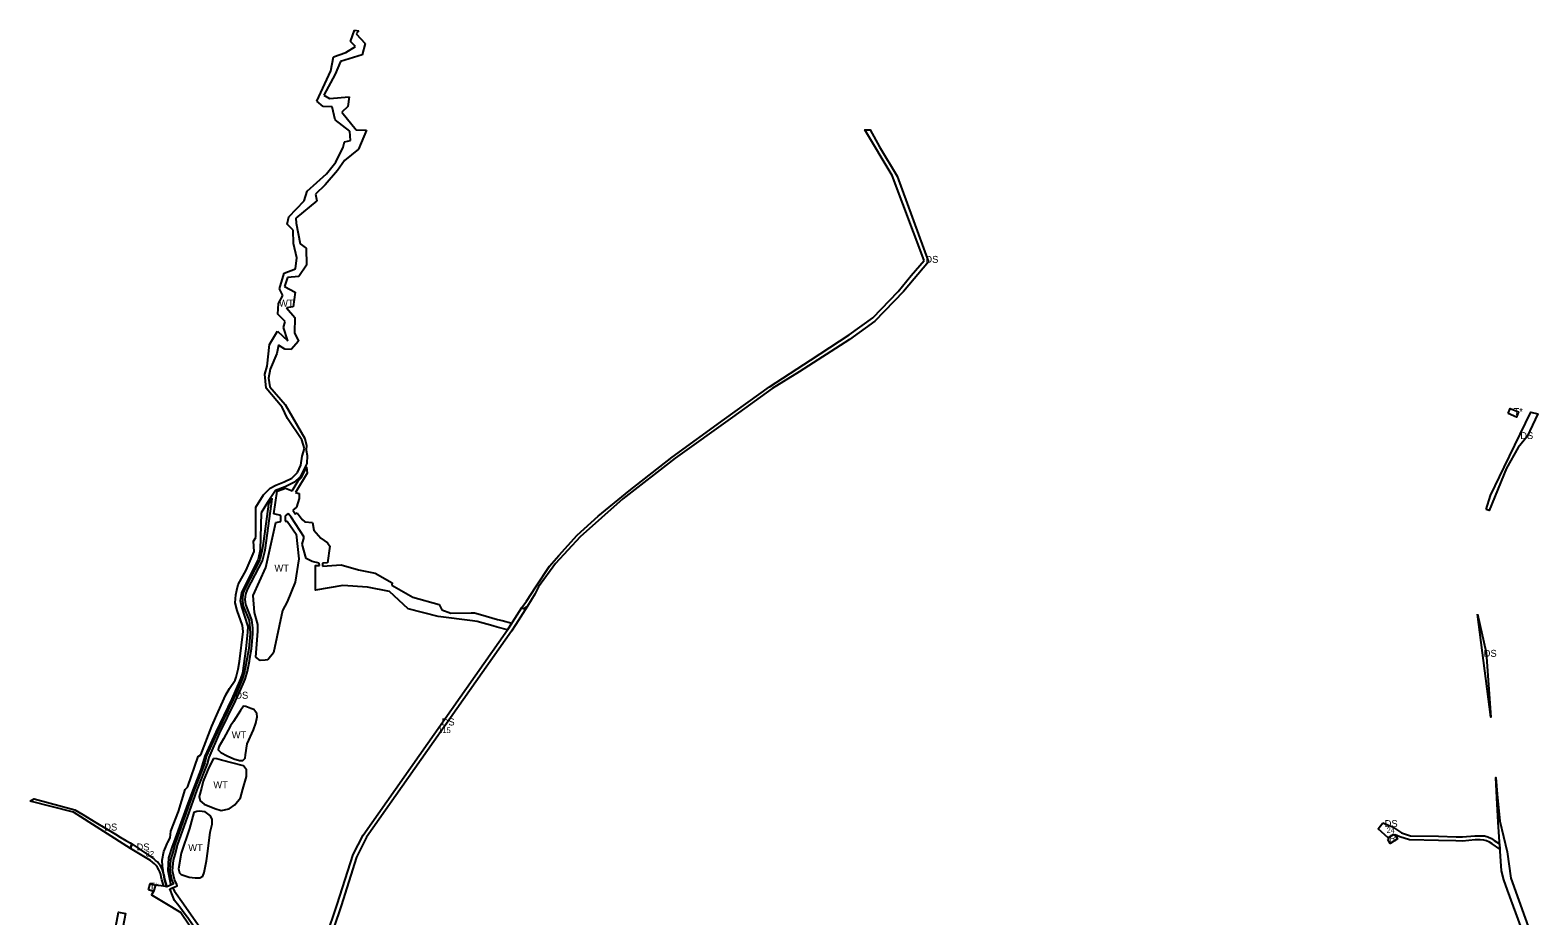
# Model space of a CAD drawing. Extents: x -521621 to -516769, y -1190068 to -1185078.
# Drawn here: x -519100 to -516936, y -1186349 to -1185078 of the extents above; entities that cross this region are included whole.
import ezdxf

# ---------------------------------------------------------------- set-up
doc = ezdxf.new("R2010")
doc.units = 0
for name, color, linetype in [('fpl_id', 7, 'Continuous'), ('rekreace_s', 7, 'Continuous'), ('v_infrastr_n', 7, 'Continuous'), ('v_infrastr_s', 7, 'Continuous'), ('voda_s', 7, 'Continuous')]:
    doc.layers.add(name, color=color, linetype=linetype)

msp = doc.modelspace()

# ---------------------------------------------------------------- linework, layer by layer
at = {"layer": 'rekreace_s'}
msp.add_lwpolyline([(-517151.5, -1186239.8), (-517150.1, -1186238.9), (-517150.8, -1186237.4), (-517145.5, -1186234), (-517143, -1186232.4), (-517142.2, -1186233.7), (-517140.8, -1186232.9), (-517137.3, -1186238.9), (-517142.6, -1186242.1), (-517148, -1186245.4)], close=True, dxfattribs=at)
at = {"layer": 'v_infrastr_n'}
for points in [[(-518690.9, -1186426.8), (-518659.5, -1186333), (-518636.5, -1186261.5), (-518622.2, -1186233.6), (-518414.9, -1185939), (-518414.9, -1185939), (-518408.8, -1185929.5), (-518407.8, -1185928), (-518394.2, -1185906.7), (-518391.7, -1185908.5), (-518385.9, -1185904.8), (-518402.8, -1185931.3), (-518409.2, -1185940.6), (-518409.2, -1185940.6), (-518409.2, -1185940.6), (-518617, -1186236.6), (-518631.4, -1186265.3), (-518653.7, -1186334.8), (-518685.1, -1186428.3)], [(-518927.4, -1186270), (-518955.8, -1186252.5), (-518953.9, -1186246.2), (-518922.6, -1186267.6)], [(-518908.2, -1186290.1), (-518907.1, -1186296.6), (-518903.9, -1186307.5), (-518908.2, -1186306.9), (-518911, -1186297.5), (-518911.7, -1186293.4)], [(-518980.6, -1186385), (-518973, -1186343.9), (-518963.1, -1186345.8), (-518970.7, -1186386.2)]]:
    msp.add_lwpolyline(points, dxfattribs=at)
msp.add_lwpolyline([(-517158.3, -1186215.8), (-517144.5, -1186221.5), (-517131.5, -1186230.4), (-517119, -1186234.4), (-517078.5, -1186235.2), (-517053.4, -1186235.8), (-517044.3, -1186236), (-517026.4, -1186234.3), (-517018.4, -1186234.3), (-517012.7, -1186234.7), (-517007.6, -1186235.8), (-517002.6, -1186238.4), (-516998.5, -1186241.1), (-516990.9, -1186246.1), (-516990.4, -1186253.6), (-517001.8, -1186246.1), (-517005.6, -1186243.6), (-517009.6, -1186241.5), (-517013.5, -1186240.7), (-517018.6, -1186240.3), (-517026.2, -1186240.3), (-517044, -1186242), (-517053.5, -1186241.8), (-517078.7, -1186241.2), (-517120, -1186240.3), (-517134.1, -1186235.8), (-517140.8, -1186232.9), (-517142.2, -1186233.7), (-517143, -1186232.4), (-517145.5, -1186234), (-517150.8, -1186237.4), (-517165.1, -1186224.3)], close=True, dxfattribs=at)
for centre, end in [((-518945.2, -1186299), 58.3971), ((-518941.7, -1186295.7), 55.7376)]:
    msp.add_arc(centre, 34, 9.5068, end, dxfattribs=at)
at = {"layer": 'v_infrastr_s'}
for points in [[(-517816.9, -1185408.7), (-517862.7, -1185286.7), (-517901.9, -1185221.3), (-517894.5, -1185221.5), (-517880.7, -1185245.8), (-517855.4, -1185287.8), (-517810.6, -1185410.6)], [(-517810.6, -1185410.6), (-517846.7, -1185453.4), (-517887.7, -1185495.7), (-517923.9, -1185522.2), (-517996.1, -1185568.4), (-518034.8, -1185592.7), (-518092, -1185633.6), (-518174.4, -1185692.5), (-518249.2, -1185750.8), (-518310.7, -1185805.2), (-518345.9, -1185843.6), (-518370.1, -1185877.1), (-518375.8, -1185887.9), (-518385.9, -1185904.8), (-518391.7, -1185908.5), (-518394.2, -1185906.7), (-518387.5, -1185897.9), (-518374.2, -1185877.1), (-518354.7, -1185847.4), (-518341, -1185832.2), (-518314.8, -1185803), (-518284.9, -1185775.7), (-518240.3, -1185739.3), (-518178.6, -1185690.9), (-518103.6, -1185636.4), (-518038.7, -1185589.9), (-517979.9, -1185551.7), (-517924.4, -1185515.4), (-517890.5, -1185491), (-517854.2, -1185453.3), (-517835.5, -1185430.5), (-517816.9, -1185408.7)], [(-518899.6, -1186310.7), (-518892.4, -1186307.8), (-518888.7, -1186306.2), (-518889.5, -1186304.3), (-518892.6, -1186297.4), (-518895.6, -1186284.9), (-518894.4, -1186269.4), (-518891.9, -1186261.1), (-518889.1, -1186250.5), (-518888.8, -1186249.4), (-518888.1, -1186246.5), (-518874.1, -1186207.7), (-518860.1, -1186168.7), (-518845.2, -1186131.1), (-518843.2, -1186122), (-518828.1, -1186087.7), (-518805.2, -1186040.7), (-518798.8, -1186027.3), (-518791.5, -1186009.9), (-518788, -1185998.1), (-518785.3, -1185983.8), (-518784.5, -1185979.7), (-518782.3, -1185966.3), (-518780.1, -1185944.8), (-518780.5, -1185936.1), (-518781.6, -1185924.7), (-518790.6, -1185902.7), (-518791.4, -1185895.5), (-518790.5, -1185887.9), (-518787.8, -1185880.8), (-518766.7, -1185839.7), (-518762.8, -1185824.5), (-518759.5, -1185800.1), (-518752.8, -1185751), (-518757.9, -1185758.6), (-518765.1, -1185811.7), (-518766.8, -1185824), (-518770.5, -1185838.3), (-518791.4, -1185879.2), (-518794.5, -1185886.9), (-518795.4, -1185895.5), (-518794.5, -1185903.7), (-518785.5, -1185925.6), (-518784.5, -1185936.4), (-518784.1, -1185944.7), (-518786.3, -1185965.8), (-518789.3, -1185983.9), (-518791.9, -1185997.2), (-518795.3, -1186008.6), (-518802.4, -1186025.7), (-518808.8, -1186038.9), (-518831.7, -1186086.1), (-518847.1, -1186120.8), (-518849, -1186129.9), (-518863.9, -1186167.3), (-518877.8, -1186206.3), (-518891.9, -1186245.3), (-518892.7, -1186248.4), (-518893, -1186249.5), (-518895.7, -1186260), (-518898.4, -1186268.6), (-518899.7, -1186285.2), (-518896.5, -1186298.8), (-518894.3, -1186303.6), (-518901.3, -1186306.6)], [(-516959.1, -1186368.4), (-516979.8, -1186312.4), (-516984.9, -1186297.8), (-516988.4, -1186284.6), (-516992.8, -1186215.1), (-516994.8, -1186179.8), (-516996.5, -1186151), (-516994.5, -1186174.9), (-516990.7, -1186213.6), (-516980.2, -1186257.6), (-516974.7, -1186295.2), (-516942.5, -1186384.5)], [(-518903.9, -1186307.5), (-518908.2, -1186306.9), (-518920.2, -1186305.2), (-518923, -1186314.6), (-518925.7, -1186319.4), (-518906.6, -1186330.5), (-518883.8, -1186344.5)], [(-518901.3, -1186306.6), (-518903.9, -1186307.5)], [(-518898.1, -1186314.1), (-518899.6, -1186310.7)], [(-518892.7, -1186327.1), (-518896.7, -1186317.6), (-518898.1, -1186314.1)], [(-518886.5, -1186334.8), (-518892.7, -1186327.1)], [(-518875.8, -1186349.3), (-518886.5, -1186334.8)], [(-518883.8, -1186344.5), (-518871.5, -1186362.2), (-518869.8, -1186364.9)], [(-518866.5, -1186362.9), (-518873.4, -1186352.4), (-518875.8, -1186349.3)]]:
    msp.add_lwpolyline(points, dxfattribs=at)
for points in [[(-517010.3, -1185766.1), (-517003.8, -1185745.9), (-516984.2, -1185705.3), (-516946, -1185626.5), (-516936, -1185628.7), (-516951.5, -1185661.5), (-516964.2, -1185677.4), (-516981.2, -1185707), (-517005.8, -1185767.5)], [(-516978.4, -1185628.6), (-516975.5, -1185621.2), (-516963.8, -1185626.2), (-516966.7, -1185633.6)], [(-517022.7, -1185916.5), (-517010.1, -1185971.5), (-517003.7, -1186064.1)], [(-519099.9, -1186184.6), (-519094.2, -1186181.5), (-519036, -1186197.2), (-519024.4, -1186204.1), (-519005.5, -1186215.4), (-518977.5, -1186232.1), (-518970.6, -1186236.3), (-518962.5, -1186241.1), (-518956.5, -1186244.7), (-518953.9, -1186246.2), (-518955.8, -1186252.5), (-519037.6, -1186200.4)], [(-518930.2, -1186312.1), (-518927.7, -1186303.2), (-518920.2, -1186305.2), (-518923, -1186314.6)]]:
    msp.add_lwpolyline(points, close=True, dxfattribs=at)
at = {"layer": 'voda_s'}
for p, q in [((-518750.4, -1185772.2), (-518745.2, -1185739.9)), ((-518745.2, -1185739.9), (-518733.6, -1185735.7)), ((-518733.6, -1185735.7), (-518724, -1185739.6)), ((-518719.1, -1185741.6), (-518714, -1185743.3)), ((-518714, -1185743.3), (-518714, -1185750.5)), ((-518717.6, -1185763), (-518723.1, -1185767.3)), ((-518723.1, -1185767.3), (-518719.1, -1185772.9)), ((-518714, -1185750.5), (-518717.6, -1185763)), ((-518761.5, -1185849.5), (-518747.5, -1185785)), ((-518740.3, -1185774.9), (-518750.4, -1185772.2)), ((-518747.5, -1185785), (-518742.6, -1185783.7)), ((-518742.6, -1185783.7), (-518740.3, -1185783.4)), ((-518740.3, -1185783.4), (-518740.3, -1185774.9)), ((-518729.6, -1185771.8), (-518734.1, -1185775.2)), ((-518734.1, -1185775.2), (-518734, -1185782.9)), ((-518734, -1185782.9), (-518730.9, -1185783)), ((-518730.9, -1185783), (-518718.1, -1185801.6)), ((-518725.4, -1185777.3), (-518729.6, -1185771.8)), ((-518706.8, -1185805.8), (-518725.4, -1185777.3)), ((-518719.1, -1185772.9), (-518716.7, -1185771)), ((-518716.7, -1185771), (-518709.5, -1185780.3)), ((-518709.5, -1185780.3), (-518705.7, -1185783.7)), ((-518705.7, -1185783.7), (-518694.8, -1185784.9)), ((-518694.8, -1185784.9), (-518692.8, -1185795.9)), ((-518718.1, -1185801.6), (-518714.4, -1185836.8)), ((-518709.5, -1185816), (-518706.8, -1185805.8)), ((-518692.8, -1185795.9), (-518682.7, -1185807.1)), ((-518682.7, -1185807.1), (-518673.3, -1185814.2)), ((-518703.8, -1185836.4), (-518709.5, -1185816)), ((-518673.3, -1185814.2), (-518669.7, -1185819)), ((-518669.7, -1185819), (-518673.1, -1185842.6)), ((-518780, -1185889.4), (-518761.5, -1185849.5)), ((-518714.4, -1185836.8), (-518719.6, -1185870.3)), ((-518695.4, -1185841), (-518703.8, -1185836.4)), ((-518684.9, -1185843.4), (-518695.4, -1185841)), ((-518684.8, -1185846.7), (-518684.9, -1185843.4)), ((-518680.4, -1185843.2), (-518680.5, -1185847.3)), ((-518673.1, -1185842.6), (-518680.4, -1185843.2)), ((-518719.6, -1185870.3), (-518731.2, -1185898.6)), ((-518778.1, -1185914.1), (-518780, -1185889.4)), ((-518773.2, -1185931.2), (-518778.1, -1185914.1)), ((-518737.6, -1185910.9), (-518750.6, -1185972)), ((-518731.2, -1185898.6), (-518737.6, -1185910.9)), ((-518775.8, -1185978.3), (-518773.3, -1185940.7)), ((-518773.3, -1185940.7), (-518773.2, -1185931.2)), ((-518769.8, -1185983.1), (-518775.8, -1185978.3)), ((-518762.4, -1185982.6), (-518769.8, -1185983.1)), ((-518758.7, -1185982), (-518762.4, -1185982.6)), ((-518750.6, -1185972), (-518758.7, -1185982))]:
    msp.add_line(p, q, dxfattribs=at)
for points in [[(-518640.3, -1185094.6), (-518634.5, -1185078.2)], [(-518632.8, -1185101.8), (-518640.3, -1185094.6)], [(-518634.5, -1185078.2), (-518628.2, -1185079.1)], [(-518628.2, -1185079.1), (-518631.8, -1185083.3)], [(-518631.8, -1185083.3), (-518619.1, -1185097.2)], [(-518619.1, -1185097.2), (-518623.6, -1185113.5)], [(-518668.5, -1185136.6), (-518664.4, -1185116.4)], [(-518664.4, -1185116.4), (-518646.7, -1185110.4)], [(-518623.6, -1185113.5), (-518654.5, -1185123)], [(-518646.7, -1185110.4), (-518632.8, -1185101.8)], [(-518688.7, -1185180), (-518668.5, -1185136.6)], [(-518662.2, -1185141.2), (-518678.3, -1185171.7)], [(-518654.5, -1185123), (-518662.2, -1185141.2)], [(-518679.2, -1185187.8), (-518688.7, -1185180)], [(-518678.3, -1185171.7), (-518670.5, -1185176.5)], [(-518670.5, -1185176.5), (-518642.3, -1185173.9)], [(-518642.3, -1185173.9), (-518644, -1185188)], [(-518666.5, -1185188.5), (-518679.2, -1185187.8)], [(-518662.2, -1185206.8), (-518666.5, -1185188.5)], [(-518644, -1185188), (-518652.5, -1185195.8)], [(-518652.5, -1185195.8), (-518632.1, -1185221.3)], [(-518641.1, -1185223.3), (-518662.2, -1185206.8)], [(-518640, -1185236.4), (-518641.1, -1185223.3)], [(-518632.1, -1185221.3), (-518617, -1185221.6)], [(-518617, -1185221.6), (-518628.9, -1185248.8)], [(-518661.3, -1185267.7), (-518650.9, -1185246)], [(-518650.9, -1185246), (-518649, -1185238.7)], [(-518649, -1185238.7), (-518640, -1185236.4)], [(-518628.9, -1185248.8), (-518648.8, -1185265.2)], [(-518674.7, -1185284.4), (-518661.3, -1185267.7)], [(-518648.8, -1185265.2), (-518658.7, -1185279.5)], [(-518702.4, -1185309.1), (-518674.7, -1185284.4)], [(-518658.7, -1185279.5), (-518676.5, -1185300.3)], [(-518706.8, -1185323), (-518702.4, -1185309.1)], [(-518676.5, -1185300.3), (-518690.4, -1185313.6)], [(-518690.4, -1185313.6), (-518688.3, -1185323.1)], [(-518728.5, -1185346.1), (-518706.8, -1185323)], [(-518688.3, -1185323.1), (-518718.7, -1185348.2)], [(-518731.1, -1185356.7), (-518728.5, -1185346.1)], [(-518722.4, -1185365.5), (-518731.1, -1185356.7)], [(-518718.7, -1185348.2), (-518718, -1185355.2)], [(-518718, -1185355.2), (-518712.2, -1185385)], [(-518722.2, -1185384.6), (-518722.4, -1185365.5)], [(-518717.3, -1185405.2), (-518722.2, -1185384.6)], [(-518712.2, -1185385), (-518703.9, -1185391)], [(-518703.9, -1185391), (-518703.4, -1185415.3)], [(-518735.5, -1185426.8), (-518719.2, -1185421)], [(-518719.2, -1185421), (-518717.3, -1185405.2)], [(-518703.4, -1185415.3), (-518714.3, -1185431.6)], [(-518742.3, -1185449.3), (-518735.5, -1185426.8)], [(-518730.6, -1185433.4), (-518735, -1185446.2)], [(-518714.3, -1185431.6), (-518730.6, -1185433.4)], [(-518743.4, -1185470.5), (-518737.3, -1185458.9)], [(-518737.3, -1185458.9), (-518742.3, -1185449.3)], [(-518735, -1185446.2), (-518719.8, -1185454.3)], [(-518719.8, -1185454.3), (-518722.3, -1185475.2)], [(-518744.6, -1185485.8), (-518743.4, -1185470.5)], [(-518733.9, -1185496.4), (-518744.6, -1185485.8)], [(-518722.3, -1185475.2), (-518731.8, -1185476.7)], [(-518731.8, -1185476.7), (-518720.2, -1185490.4)], [(-518736.2, -1185504.9), (-518733.9, -1185496.4)], [(-518730.1, -1185524.1), (-518736.2, -1185504.9)], [(-518720.2, -1185490.4), (-518720.7, -1185512.7)], [(-518759.8, -1185560.5), (-518756.2, -1185529.3)], [(-518756.2, -1185529.3), (-518745, -1185510.1)], [(-518743.5, -1185530.5), (-518746.1, -1185542.5)], [(-518745, -1185510.1), (-518730.1, -1185524.1)], [(-518734.6, -1185536), (-518743.5, -1185530.5)], [(-518715, -1185524.7), (-518725.3, -1185536.6)], [(-518720.7, -1185512.7), (-518715, -1185524.7)], [(-518746.1, -1185542.5), (-518755.4, -1185564.8)], [(-518725.3, -1185536.6), (-518734.6, -1185536)], [(-518762.9, -1185571.8), (-518759.8, -1185560.5)], [(-518761.4, -1185592.1), (-518762.9, -1185571.8)], [(-518755.4, -1185564.8), (-518757.7, -1185577.5)], [(-518738.2, -1185619.3), (-518761.4, -1185592.1)], [(-518757.7, -1185577.5), (-518755.7, -1185590.2)], [(-518755.7, -1185590.2), (-518734, -1185615.4)], [(-518734, -1185615.4), (-518705.5, -1185664.1)], [(-518730.6, -1185635.4), (-518738.2, -1185619.3)], [(-518710, -1185666.2), (-518730.6, -1185635.4)], [(-518706.4, -1185678.7), (-518710, -1185666.2)], [(-518709.4, -1185689.6), (-518706.4, -1185678.7)], [(-518705.5, -1185664.1), (-518703.3, -1185674.1)], [(-518703.3, -1185674.1), (-518704, -1185681.2)], [(-518704, -1185681.2), (-518702.2, -1185688.5)], [(-518716, -1185712.9), (-518711.5, -1185702.5)], [(-518703, -1185700.3), (-518712.3, -1185719.5)], [(-518711.5, -1185702.5), (-518709.4, -1185689.6)], [(-518702.2, -1185688.5), (-518703, -1185700.3)], [(-518735.4, -1185726.7), (-518724.3, -1185721.3)], [(-518724.3, -1185721.3), (-518716, -1185712.9)], [(-518724, -1185739.6), (-518715.5, -1185725), (-518710.8, -1185720.9), (-518706.2, -1185711.8), (-518703.4, -1185705.5), (-518703.4, -1185705.5), (-518702.4, -1185714), (-518719.1, -1185741.6)], [(-518712.3, -1185719.5), (-518720.6, -1185726.8)], [(-518776.1, -1185762.9), (-518765.2, -1185745.3)], [(-518765.2, -1185745.3), (-518755.3, -1185735.5)], [(-518747.9, -1185739), (-518759.1, -1185756)], [(-518755.3, -1185735.5), (-518747.5, -1185731.2)], [(-518733.8, -1185733.5), (-518747.9, -1185739)], [(-518747.5, -1185731.2), (-518735.4, -1185726.7)], [(-518720.6, -1185726.8), (-518733.8, -1185733.5)], [(-518775.8, -1185787.2), (-518776.1, -1185762.9)], [(-518759.1, -1185756), (-518768.5, -1185770.8)], [(-518775.9, -1185806.2), (-518775.8, -1185787.2)], [(-518768.5, -1185770.8), (-518769.8, -1185824.1)], [(-518779.4, -1185811.4), (-518775.9, -1185806.2)], [(-518778.6, -1185826.6), (-518779.4, -1185811.4)], [(-518790.1, -1185853.2), (-518781.2, -1185833.3)], [(-518781.2, -1185833.3), (-518778.6, -1185826.6)], [(-518769.8, -1185824.1), (-518772.5, -1185837.7)], [(-518801.4, -1185873.7), (-518790.1, -1185853.2)], [(-518772.5, -1185837.7), (-518796.8, -1185885.4)], [(-518651.1, -1185875.4), (-518690.5, -1185881.8), (-518690.4, -1185879.5), (-518690.5, -1185846.7), (-518684.8, -1185846.7)], [(-518680.5, -1185847.3), (-518653.6, -1185845.4)], [(-518653.6, -1185845.4), (-518628.8, -1185852.7)], [(-518628.8, -1185852.7), (-518604.8, -1185857.3)], [(-518803.2, -1185881.9), (-518801.4, -1185873.7)], [(-518615.6, -1185877.8), (-518651.1, -1185875.4)], [(-518604.8, -1185857.3), (-518580.5, -1185871.4)], [(-518580.5, -1185871.4), (-518581, -1185874.9)], [(-518581, -1185874.9), (-518550.9, -1185891.8)], [(-518805.6, -1185899.9), (-518804.9, -1185888.6)], [(-518804.9, -1185888.6), (-518803.2, -1185881.9)], [(-518796.8, -1185885.4), (-518798.3, -1185896.8)], [(-518798.3, -1185896.8), (-518796.4, -1185905.8)], [(-518584.4, -1185884), (-518615.6, -1185877.8)], [(-518557.2, -1185908.5), (-518584.4, -1185884)], [(-518550.9, -1185891.8), (-518512.8, -1185902.5)], [(-518802.6, -1185910.9), (-518805.6, -1185899.9)], [(-518795, -1185932.8), (-518802.6, -1185910.9)], [(-518796.4, -1185905.8), (-518787.7, -1185934.1)], [(-518514.5, -1185919.6), (-518557.2, -1185908.5)], [(-518465.2, -1185926.1), (-518514.5, -1185919.6)], [(-518512.8, -1185902.5), (-518509, -1185910.2)], [(-518509, -1185910.2), (-518496.1, -1185915)], [(-518496.1, -1185915), (-518466.8, -1185914.7)], [(-518466.8, -1185914.7), (-518462.2, -1185914.5), (-518453.5, -1185916.9), (-518429.2, -1185923.9), (-518422.6, -1185925.6), (-518408.8, -1185929.5)], [(-518799.4, -1185984.2), (-518794.2, -1185941.2)], [(-518794.2, -1185941.2), (-518795, -1185932.8)], [(-518787.7, -1185934.1), (-518788, -1185942.3)], [(-518414.9, -1185939), (-518429.7, -1185934.8), (-518435.9, -1185933.1), (-518458.5, -1185926.8), (-518465.2, -1185926.1)], [(-518408.8, -1185929.5), (-518414.9, -1185939)], [(-518788, -1185942.3), (-518790.3, -1185965.9)], [(-518801.4, -1185995.2), (-518799.4, -1185984.2)], [(-518790.3, -1185965.9), (-518795.3, -1186001.1)], [(-518805.6, -1186011.3), (-518804.2, -1186006.7)], [(-518804.2, -1186006.7), (-518801.4, -1185995.2)], [(-518795.3, -1186001.1), (-518797.8, -1186009.1)], [(-518819.2, -1186032.3), (-518813.9, -1186023.1)], [(-518813.9, -1186023.1), (-518805.6, -1186011.3)], [(-518797.8, -1186009.1), (-518810.7, -1186037.8)], [(-518810.7, -1186037.8), (-518833.6, -1186085.6)], [(-518830, -1186056.4), (-518819.2, -1186032.3)], [(-518839, -1186077.3), (-518830, -1186056.4)], [(-518855, -1186118.2), (-518839, -1186077.3)], [(-518833.6, -1186085.6), (-518849, -1186120)], [(-518903.9, -1186307.5), (-518907.1, -1186296.6), (-518910.2, -1186277.8), (-518910.4, -1186269.2), (-518908.2, -1186257), (-518905.4, -1186250.1), (-518903.1, -1186245.4), (-518902.7, -1186244.5), (-518899.2, -1186237.6), (-518898, -1186227.9), (-518886.8, -1186199.7), (-518877.6, -1186168.2), (-518873.9, -1186164.7), (-518873.6, -1186163.8), (-518859, -1186120.6), (-518855, -1186118.2)], [(-518849, -1186120), (-518855.2, -1186139.4)], [(-518855.2, -1186139.4), (-518865.5, -1186166.5)], [(-518865.5, -1186166.5), (-518873.6, -1186188.2)], [(-518873.6, -1186188.2), (-518892, -1186238.4)], [(-518892, -1186238.4), (-518895, -1186247.5)], [(-518901.2, -1186266.3), (-518902.3, -1186284.4)], [(-518895.4, -1186248.6), (-518901.2, -1186266.3)], [(-518895, -1186247.5), (-518895.4, -1186248.6)], [(-518902.3, -1186284.4), (-518898.6, -1186303.3)], [(-518901.3, -1186306.6), (-518903.9, -1186307.5)], [(-518897.7, -1186305), (-518901.3, -1186306.6)], [(-518899.6, -1186310.7), (-518895.6, -1186309.1)], [(-518898.6, -1186303.3), (-518897.7, -1186305)], [(-518895.6, -1186309.1), (-518895.3, -1186309.5)], [(-518895.3, -1186309.5), (-518893, -1186313.9)], [(-518898.1, -1186314.1), (-518899.6, -1186310.7)], [(-518896.7, -1186317.6), (-518898.1, -1186314.1)], [(-518892.7, -1186327.1), (-518896.7, -1186317.6)], [(-518893, -1186313.9), (-518879.8, -1186331.9)], [(-518886.5, -1186334.8), (-518892.7, -1186327.1)], [(-518875.8, -1186349.3), (-518886.5, -1186334.8)], [(-518879.8, -1186331.9), (-518855.4, -1186367.1)], [(-518849, -1186414.4), (-518853, -1186396.8), (-518854.8, -1186387.1), (-518857.2, -1186378.1), (-518861.9, -1186369.8), (-518873.4, -1186352.4), (-518875.8, -1186349.3)]]:
    msp.add_lwpolyline(points, dxfattribs=at)
for points in [[(-518790.5, -1186048.7), (-518793.8, -1186048.5), (-518797.8, -1186054.5), (-518808.2, -1186070.4), (-518812.6, -1186076.8), (-518822.6, -1186095.4), (-518829.3, -1186106.6), (-518829.9, -1186111.2), (-518826.3, -1186114.8), (-518817, -1186119.8), (-518807.6, -1186123.9), (-518799.7, -1186126.2), (-518794.9, -1186126.4), (-518791.3, -1186123.1), (-518790.7, -1186118.3), (-518788.6, -1186102.7), (-518779.5, -1186082.5), (-518776.1, -1186072.9), (-518774.2, -1186063.9), (-518774.7, -1186059.1), (-518778.8, -1186053.3), (-518783, -1186051.6)], [(-518837, -1186123.5), (-518843.4, -1186136.6), (-518851.4, -1186156.2), (-518854.1, -1186166.2), (-518857.6, -1186178.1), (-518856.1, -1186184.2), (-518850.3, -1186189.2), (-518834.9, -1186195.4), (-518825.7, -1186198.1), (-518814.1, -1186195.8), (-518806.1, -1186190), (-518798, -1186180), (-518794.5, -1186167.3), (-518789.2, -1186149.2), (-518789.2, -1186140), (-518793.8, -1186134.2), (-518825.1, -1186125.9), (-518832, -1186124)], [(-518860.7, -1186199.6), (-518864.9, -1186200.8), (-518871.4, -1186223.8), (-518883.3, -1186259.2), (-518886.8, -1186281.9), (-518885.7, -1186287.5), (-518883.2, -1186290.2), (-518871.8, -1186294), (-518863, -1186294.6), (-518856.6, -1186294.6), (-518852.2, -1186292.5), (-518850.3, -1186287.3), (-518846.6, -1186270.4), (-518845.1, -1186256.5), (-518841.4, -1186229.2), (-518838.6, -1186217.9), (-518838.6, -1186211), (-518840.9, -1186205.6), (-518848.6, -1186200.2), (-518857.2, -1186199)]]:
    msp.add_lwpolyline(points, close=True, dxfattribs=at)

# ---------------------------------------------------------------- texts
at = {"layer": 'fpl_id'}
for s, p in [('115', (-518514.2, -1186087)), ('24', (-517153.1, -1186230.5)), ('32', (-518934, -1186264.3))]:
    msp.add_text(s, height=8, dxfattribs=at).set_placement(p)
at = {"layer": 'rekreace_s'}
msp.add_text('R', height=10, dxfattribs=at).set_placement((-517149, -1186242.7))
at = {"layer": 'v_infrastr_n'}
for p in [(-518509.3, -1186076.1), (-517155.8, -1186221.9), (-518947.2, -1186255.5)]:
    msp.add_text('DS', height=10, dxfattribs=at).set_placement(p)
at = {"layer": 'v_infrastr_s'}
for s, p in [('DS', (-517815, -1185412.2)), ('T*', (-516970.9, -1185630.6)), ('DS', (-516961.3, -1185665)), ('DS', (-517013.7, -1185977.6)), ('DS', (-518805.5, -1186037.8)), ('DS', (-518993.5, -1186226.9)), ('T*', (-518928.9, -1186311.9))]:
    msp.add_text(s, height=10, dxfattribs=at).set_placement(p)
at = {"layer": 'voda_s'}
for p in [(-518742.6, -1185475.1), (-518749.3, -1185855.3), (-518810.6, -1186094.6), (-518837, -1186166.1), (-518873, -1186256.5)]:
    msp.add_text('WT', height=10, dxfattribs=at).set_placement(p)

doc.saveas('drawing.dxf')
